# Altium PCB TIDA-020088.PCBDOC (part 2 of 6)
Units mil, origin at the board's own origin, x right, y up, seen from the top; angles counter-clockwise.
Board outline 7520.69 x 5119.11 mil, 6 copper layers (TOP, GND02, SIG03, SIG04, GND05, BOTTOM), stack 87.024 mil thick; 539 components, 269 nets, 1479 pads, 2085 vias.
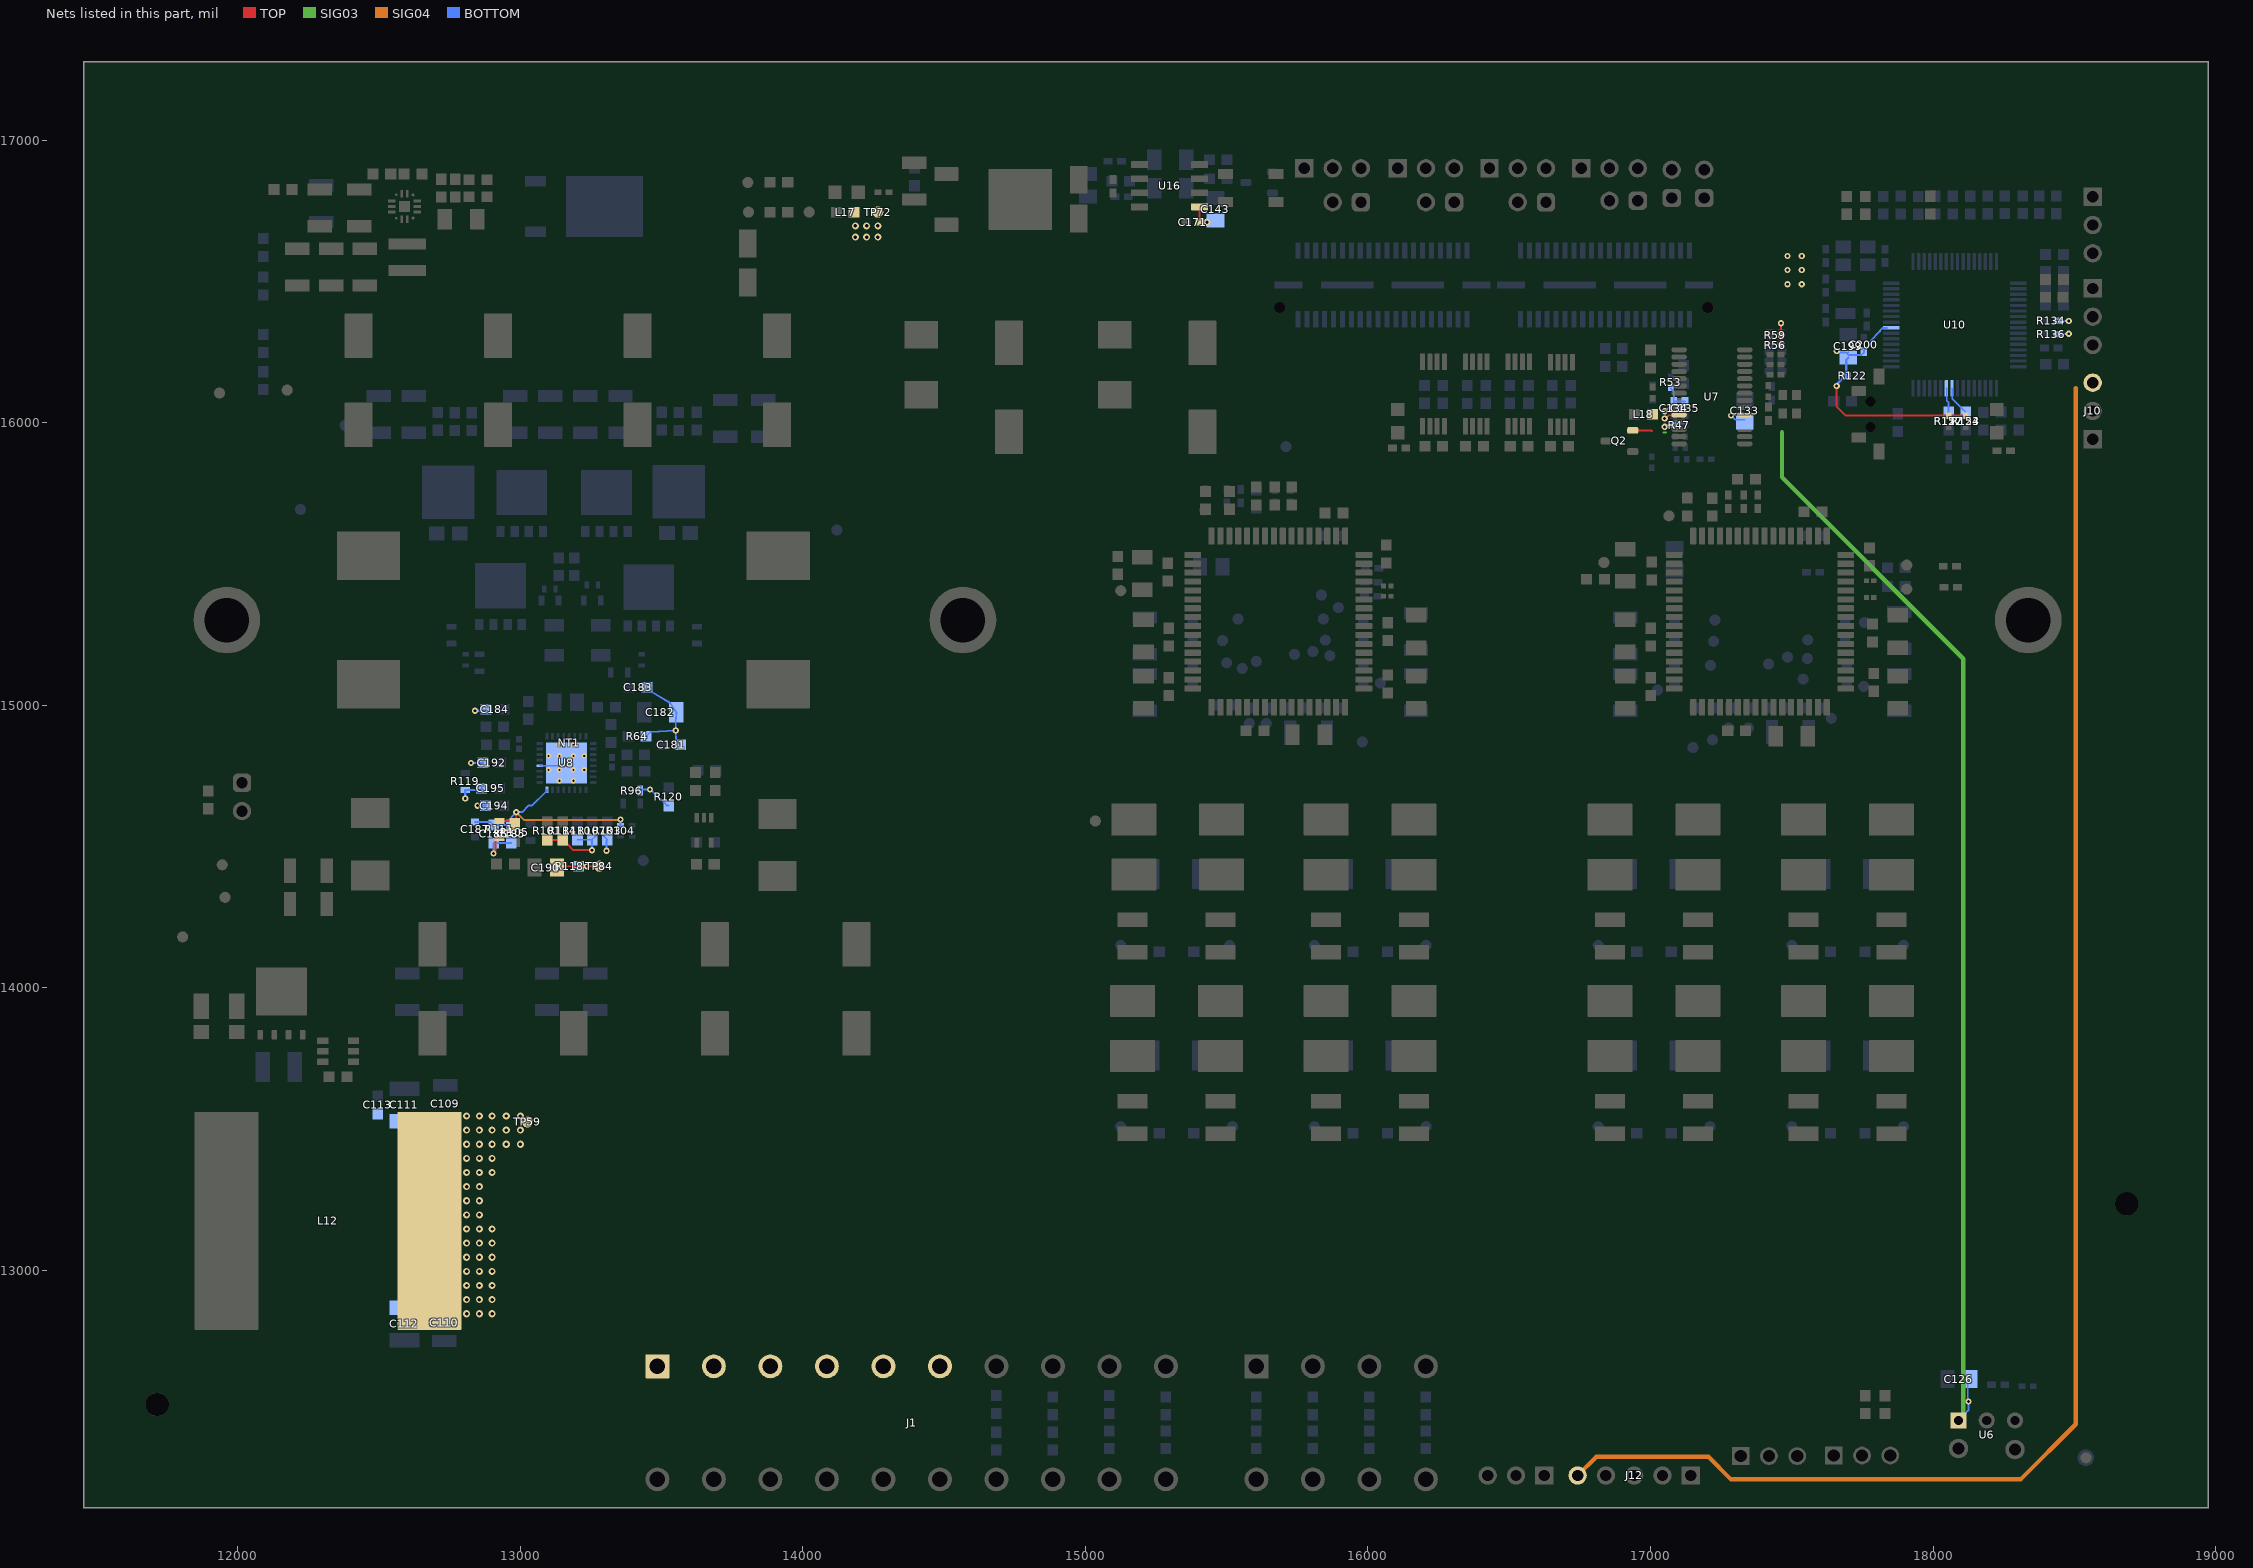
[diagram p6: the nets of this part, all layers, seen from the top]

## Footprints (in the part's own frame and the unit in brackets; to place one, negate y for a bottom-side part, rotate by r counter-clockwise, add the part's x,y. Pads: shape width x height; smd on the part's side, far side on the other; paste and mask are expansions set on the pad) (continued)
PM0064A-MFG [mm]
  rrect33% 1.5x0.3 smd paste+0 mask+0: 1(-5.7,3.75) 2(-5.7,3.25) 3(-5.7,2.75) 4(-5.7,2.25) 5(-5.7,1.75) 6(-5.7,1.25) 7(-5.7,0.75) 8(-5.7,0.25) 9(-5.7,-0.25) 10(-5.7,-0.75) 11(-5.7,-1.25) 12(-5.7,-1.75) 13(-5.7,-2.25) 14(-5.7,-2.75) 15(-5.7,-3.25) 16(-5.7,-3.75) 33(5.7,-3.75) 34(5.7,-3.25) 35(5.7,-2.75) 36(5.7,-2.25) 37(5.7,-1.75) 38(5.7,-1.25) 39(5.7,-0.75) 40(5.7,-0.25) 41(5.7,0.25) 42(5.7,0.75) 43(5.7,1.25) 44(5.7,1.75) 45(5.7,2.25) 46(5.7,2.75) 47(5.7,3.25) 48(5.7,3.75)
  rrect33% 0.3x1.5 smd paste+0 mask+0: 17(-3.75,-5.7) 18(-3.25,-5.7) 19(-2.75,-5.7) 20(-2.25,-5.7) 21(-1.75,-5.7) 22(-1.25,-5.7) 23(-0.75,-5.7) 24(-0.25,-5.7) 25(0.25,-5.7) 26(0.75,-5.7) 27(1.25,-5.7) 28(1.75,-5.7) 29(2.25,-5.7) 30(2.75,-5.7) 31(3.25,-5.7) 32(3.75,-5.7) 49(3.75,5.7) 50(3.25,5.7) 51(2.75,5.7) 52(2.25,5.7) 53(1.75,5.7) 54(1.25,5.7) 55(0.75,5.7) 56(0.25,5.7) 57(-0.25,5.7) 58(-0.75,5.7) 59(-1.25,5.7) 60(-1.75,5.7) 61(-2.25,5.7) 62(-2.75,5.7) 63(-3.25,5.7) 64(-3.75,5.7)
  silkscreen extent -7.13,-5.1 5.1,5.1, body extent -6,-6 6,6, height 1.6
PW0008A-MFG [mm]
  rrect22% 1.5x0.45 smd paste+0 mask+0: 1(-2.9,0.975) 2(-2.9,0.325) 3(-2.9,-0.325) 4(-2.9,-0.975) 5(2.9,-0.975) 6(2.9,-0.325) 7(2.9,0.325) 8(2.9,0.975)
  silkscreen extent -4.37,-1.55 1.77,1.55, body extent -3.75,-1.8 3.75,1.8, height 0.25
PW0028A_N [mm] "TSOP, 28-Leads, Body 9.7x4.4mm, Pitch 0.65mm, IPC Medium Density"
  oval 1.4x0.45 smd: 1(-2.95,4.225) 2(-2.95,3.575) 3(-2.95,2.925) 4(-2.95,2.275) 5(-2.95,1.625) 6(-2.95,0.975) 7(-2.95,0.325) 8(-2.95,-0.325) 9(-2.95,-0.975) 10(-2.95,-1.625) 11(-2.95,-2.275) 12(-2.95,-2.925) 13(-2.95,-3.575) 14(-2.95,-4.225) 15(2.95,-4.225) 16(2.95,-3.575) 17(2.95,-2.925) 18(2.95,-2.275) 19(2.95,-1.625) 20(2.95,-0.975) 21(2.95,-0.325) 22(2.95,0.325) 23(2.95,0.975) 24(2.95,1.625) 25(2.95,2.275) 26(2.95,2.925) 27(2.95,3.575) 28(2.95,4.225)
  silkscreen extent -3.5,-4.9 1.5,4.9, body extent -3.21,-4.85 3.21,4.85, height 1
RHB0032U-MFG [mm]
  rrect40% 0.6x0.25 smd paste+0 mask+0: 1(-2.4,1.75) 2(-2.4,1.25) 3(-2.4,0.75) 4(-2.4,0.25) 5(-2.4,-0.25) 6(-2.4,-0.75) 7(-2.4,-1.25) 8(-2.4,-1.75) 17(2.4,-1.75) 18(2.4,-1.25) 19(2.4,-0.75) 20(2.4,-0.25) 21(2.4,0.25) 22(2.4,0.75) 23(2.4,1.25) 24(2.4,1.75)
  rrect40% 0.25x0.6 smd paste+0 mask+0: 9(-1.75,-2.4) 10(-1.25,-2.4) 11(-0.75,-2.4) 12(-0.25,-2.4) 13(0.25,-2.4) 14(0.75,-2.4) 15(1.25,-2.4) 16(1.75,-2.4) 25(1.75,2.4) 26(1.25,2.4) 27(0.75,2.4) 28(0.25,2.4) 29(-0.25,2.4) 30(-0.75,2.4) 31(-1.25,2.4) 32(-1.75,2.4)
  rrect3% 3.7x3.7 smd paste-1000 mask+0: 33(0,0)
  silkscreen extent -3.37,-2.55 2.55,2.55, body extent -2.5,-2.5 2.5,2.5, height 1
RXB0014A-MFG [mm]
  round 0.225 smd paste+0 mask+0: 1(-0.75,1.05) 5(-0.75,-1.05)
  rrect40% 0.7x0.25 smd paste+0 mask+0: 2(-1.15,0.5) 3(-1.15,0) 4(-1.15,-0.5) 9(1.15,-0.5) 10(1.15,0) 11(1.15,0.5)
  rrect40% 0.25x0.7 smd paste+0 mask+0: 6(-0.25,-1.15) 7(0.25,-1.15) 13(0.25,1.15) 14(-0.25,1.15)
  round 0.27 smd paste+0 mask+0: 8(0.775,-1.05) 12(0.775,1.05)
  rrect10% 1x1 smd paste-1000 mask+0: 15(0,0)
  TOP region: -1.5,0.95 -1.5,1.1 -1.493,1.125 -1.475,1.143 -1.45,1.15 -1.45,1.15 -0.925,1.15 -0.906,1.154 -0.89,1.165 -0.879,1.181 -0.875,1.2 -0.875,1.2 -0.875,1.45 -0.868,1.475 -0.85,1.493 -0.825,1.5 -0.825,1.5 -0.675,1.5 -0.656,1.496 -0.64,1.485 -0.629,1.469 -0.625,1.45 -0.625,1.45 -0.625,0.95 -0.629,0.931 -0.64,0.915 -0.656,0.904 -0.675,0.9 -0.675,0.9 -1.45,0.9 -1.469,0.904 -1.485,0.915 -1.496,0.931 -1.5,0.95
  TOP region: 1.5,0.95 1.5,1.1 1.493,1.125 1.475,1.143 1.45,1.15 1.45,1.15 0.925,1.15 0.906,1.154 0.89,1.165 0.879,1.181 0.875,1.2 0.875,1.2 0.875,1.45 0.868,1.475 0.85,1.493 0.825,1.5 0.825,1.5 0.675,1.5 0.656,1.496 0.64,1.485 0.629,1.469 0.625,1.45 0.625,1.45 0.625,0.95 0.629,0.931 0.64,0.915 0.656,0.904 0.675,0.9 0.675,0.9 1.45,0.9 1.469,0.904 1.485,0.915 1.496,0.931 1.5,0.95
  TOP region: -1.5,-0.95 -1.5,-1.1 -1.493,-1.125 -1.475,-1.143 -1.45,-1.15 -1.45,-1.15 -0.925,-1.15 -0.906,-1.154 -0.89,-1.165 -0.879,-1.181 -0.875,-1.2 -0.875,-1.2 -0.875,-1.45 -0.868,-1.475 -0.85,-1.493 -0.825,-1.5 -0.825,-1.5 -0.675,-1.5 -0.656,-1.496 -0.64,-1.485 -0.629,-1.469 -0.625,-1.45 -0.625,-1.45 -0.625,-0.95 -0.629,-0.931 -0.64,-0.915 -0.656,-0.904 -0.675,-0.9 -0.675,-0.9 -1.45,-0.9 -1.469,-0.904 -1.485,-0.915 -1.496,-0.931 -1.5,-0.95
  TOP region: 1.5,-0.95 1.5,-1.1 1.493,-1.125 1.475,-1.143 1.45,-1.15 1.45,-1.15 0.925,-1.15 0.906,-1.154 0.89,-1.165 0.879,-1.181 0.875,-1.2 0.875,-1.2 0.875,-1.45 0.868,-1.475 0.85,-1.493 0.825,-1.5 0.825,-1.5 0.675,-1.5 0.656,-1.496 0.64,-1.485 0.629,-1.469 0.625,-1.45 0.625,-1.45 0.625,-0.95 0.629,-0.931 0.64,-0.915 0.656,-0.904 0.675,-0.9 0.675,-0.9 1.45,-0.9 1.469,-0.904 1.485,-0.915 1.496,-0.931 1.5,-0.95
  silkscreen extent -2.17,-1.68 1.58,1.68, body extent -1.6,-1.6 1.6,1.6, height 0.25
Samtec_HTSW-105-07-G-S [mm] "Samtec 100mil, 1x5, 230 mil above insulator"
  rrect6% 1.65x1.65 hole 1.016: 1(-5.08,0)
  round 1.65 hole 1.016: 2(-2.54,0) 3(0,0) 4(2.54,0) 5(5.08,0)
  silkscreen extent -7.11,-1.27 6.35,1.27, body extent -6.35,-1.27 6.35,1.27, height 8.38
SO-8FL [mm] "ON SEMICONDUCTOR, DFN5 5x6, 1.27P, CASE 488AA"
  rect 1x0.75 smd: 1(-2.795,1.905) 2(-2.795,0.635) 3(-2.795,-0.635) 4(-2.795,-1.905)
  rect 4.055x4.56 smd: 5(0.698,0)
  TOP region: 2.65,-2.279 2.65,-1.529 3.2,-1.529 3.2,-2.279
  TOP region: 2.655,1.531 2.655,2.281 3.2,2.281 3.2,1.531
  TOP region: -0.905,-2.775 -0.905,2.775 0,2.775 0,-2.775
  silkscreen extent -3.1,-2.6 3.1,2.9, body extent -3.17,-2.67 3.17,2.67, height 1.11
SOD-123HE [mm] "SMD, 2-Leads, Body 2.8x1.8mm"
  rect 2.3x1.4 smd: 1(-0.9,0)
  rect 1.25x1.4 smd: 2(1.425,0)
  silkscreen extent -2.7,-1.1 2,1.1, body extent -1.5,-0.97 1.5,0.97, height 1
SOT-23 [mm] "SOT23, 3-Leads, Body 2.9x1.3mm, Pitch 0.95mm, Lead Span 2.5mm, IPC Medium Density"
  rrect50% 1x0.6 smd: 1(-1.2,0.95) 2(-1.2,-0.95) 3(1.2,0)
  silkscreen extent -1.63,-1.5 0.7,1.5, body extent -1.16,-1.45 1.21,1.45, height 1
SRP2313AA [mm] "Shielded, metal alloy powder core"
  rrect2% 5.75x19.6 smd: 1(-9.125,0) 2(9.125,0)
  body extent -11.75,-11 11.75,11, height 12.61
SW_1188E [mm] "SMD, 4-Leads, Body 7.8x3.5mm"
  rrect10% 1x1.45 smd: 1(-1.1,3.375) 2(-1.1,-3.375)
  rrect11% 1.3x0.9 smd: 3(0.7,2.1) 4(0.7,-2.1)
  round 0 hole 0.9 unplated: ""(-0.35,1.15) ""(-0.35,-1.15)
  silkscreen extent -1.97,-2.28 0.95,2.28, body extent -2.55,-3.9 1.05,3.9, height 3.5
TI_Stacked_Overlay_Small [mil]
  silkscreen extent -418,-98 418,98
TO-277A [mm] "Vishay"
  rect 1.4x1.27 smd: 1(-1.04,1.83) 2(1.04,1.83)
  rect 4.72x4.8 smd: 3(0,-1.883)
  silkscreen extent -2.7,1.45 -2.4,1.75, body extent -2.35,-4.2 2.4,2.45, height 1.2
TP_SM_1MM [mm] "1mm Test Point, SMT"
  round 1 smd paste-0.5: 1(0,0)
TSW-102-07-G-S [mm] "Samtec 100mil, 1x2, 230 mil above insulator"
  rrect50% 1.65x1.65 hole 1.016: 1(-1.27,0)
  round 1.65 hole 1.016: 2(1.27,0)
  body extent -2.54,-1.27 2.54,1.27, height 8.38
ULRB22512_085 [mm] "SMD, 4-Leads, Body 6.35x3.18mm"
  rect 2.7x3.45 smd: 1(-2.8,0) 2(2.8,0)
  silkscreen extent -1,-1.72 1,1.72, body extent -3.3,-1.72 3.3,1.72, height 0.85
WEEE_Minimum [mil] "WEEElie bin"
  silkscreen extent -95,-172 99,104
Wurth_61300311021 [mm] "Header, 2.54 mm, 3x1, R/A, TH"
  rect 1.6x1.6 hole 1.1: 1(-2.54,0)
  round 1.6 hole 1.1: 2(0,0) 3(2.54,0)
  silkscreen extent -4.25,-4.04 3.81,-1.5, body extent -3.81,-10.04 3.81,0.32, height 2.55
XTAL_ABM10 [mm] "ABRACON"
  rect 0.8x0.9 smd: 1(-0.625,0.825) 2(-0.625,-0.825) 3(0.625,-0.825) 4(0.625,0.825)
  silkscreen extent -1.28,-0.13 1.05,1.52, body extent -1.05,-1.3 1.05,1.3, height 0.7

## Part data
C1 C4 C5 C9 C12 C53 C56 C57 C61 C64 C208 C210 C212 C214: library part CMP-0007139-3, "CAP, CERM, 1 uF, 25 V, +/- 10%, X7R, AEC-Q200 Grade 1, 0603", Cap_Case=0603, Manufacturer=MuRata, Supplier Part Number 1=490-10673-1-ND, TempCo=X7R, Tolerance_%=10%, Value1=Unknown, Value2=25V, ValueDisplayed=1uF
C2 C6 C10 C13 C15 C17 C54 C58 C62 C65 C67 C69 C122 C182: library part CMP-0750040-1, "CAP, CERM, 1 µF, 100 V,+/- 10%, X7R, AEC-Q200 Grade 1, 1206", Cap_Case=1206, Manufacturer=MuRata, TempCo=X7R, Tolerance_%=10%, Value2=100V, ValueDisplayed=1µF
C3 C7 C11 C14 C16 C18 C55 C59 C63 C66 C68 C70 C193 C203: library part CMP-0064935-2, "CAP, CERM, 0.1 uF, 100 V,+/- 10%, X7R, AEC-Q200 Grade 1, 0603", Cap_Case=0603, Manufacturer=MuRata, Supplier Part Number 1=490-13420-1-ND, TempCo=X7R, Tolerance_%=10%, Value1=Unknown, Value2=100V, ValueDisplayed=0.1uF
C8 C60: library part CMP-0083622-1, "CAP, CERM, 2.2 µF, 25 V,+/- 10%, X7R, AEC-Q200 Grade 1, 0805", Cap_Case=0805, Manufacturer=MuRata, Supplier Part Number 1=490-4787-1-ND, TempCo=X7R, Tolerance_%=10%, Value2=25V, ValueDisplayed=2.2µF
C19 C22 C29 C30 C37 C38 C45 C46 C71 C74 C81 C82 C89 C90 C97 C98: library part CMP-0007145-4, "CAP, CERM, 0.22 uF, 50 V, +/- 10%, X7R, AEC-Q200 Grade 1, 0603", Cap_Case=0603, Manufacturer=MuRata, Supplier Part Number 1=490-5402-1-ND, TempCo=X7R, Tolerance_%=10%, Value1=Unknown, Value2=50V, ValueDisplayed=0.22uF
C20 C21 C72 C73: library part CMP-0009660-3, "CAP, CERM, 100 pF, 25 V, +/- 10%, X7R, AEC-Q200 Grade 1, 0201", Cap_Case=0201, Manufacturer=MuRata, Supplier Part Number 1=GCM033R71E101KA03D-ND, TempCo=X7R, Tolerance_%=10%, Value1=Unknown, Value2=25V, ValueDisplayed=100pF
C23 C24 C31 C32 C39 C40 C47 C48 C75 C76 C83 C84 C91 C92 C99 C100: library part CMP-0007145-4, "CAP, CERM, 0.22 uF, 50 V, +/- 10%, X7R, AEC-Q200 Grade 1, 0603", Cap_Case=0603, Manufacturer=MuRata, PartNumber=GCM188R71H224KA64D, Supplier Part Number 1=490-5402-1-ND, TempCo=X7R, Tolerance_%=10%, Value1=Unknown, Value2=50V, ValueDisplayed=0.22uF
C25 C26 C33 C34 C41 C42 C49 C50 C77 C78 C85 C86 C93 C94 C101 C102: library part CMP-0009152-2, "CAP, CERM, 2.2 uF, 100 V, +/- 10%, X7R, AEC-Q200 Grade 1,", Cap_Case=1210_250, Manufacturer=TDK, Supplier Part Number 1=445-5866-1-ND, TempCo=X7R, Tolerance_%=10%, Value1="0.00173 ohm", Value2=100V, ValueDisplayed=2.2uF
C27 C28 C35 C36 C43 C44 C51 C52 C79 C80 C87 C88 C95 C96 C103 C104 C185 C186: library part CMP-0007082-4, "CAP, CERM, 0.01 uF, 100 V, +/- 10%, X7R, AEC-Q200 Grade 1, 0603", Cap_Case=0603, Manufacturer=TDK, Supplier Part Number 1=445-5812-1-ND, TempCo=X7R, Tolerance_%=10%, Value1="0.235428 ohm", Value2=100V, ValueDisplayed=0.01uF
C105 C138 C140: library part CMP-0007139-4, "CAP, CERM, 1 uF, 25 V, +/- 10%, X7R, AEC-Q200 Grade 1, 0603", Cap_Case=0603, Manufacturer=MuRata, Supplier Part Number 1=490-10673-1-ND, TempCo=X7R, Tolerance_%=10%, Value1=Unknown, Value2=25V, ValueDisplayed=1uF
C106 C114: library part CMP-0860542-1, "CAP, AL, 47 µF, 16 V, +/- 20%, 0.85 ohm, AEC-Q200 Grade 2, SMD", Cap_Case=B, Manufacturer=Panasonic, Tolerance_%=20%, Value1="0.85 ohm", Value2=16V, ValueDisplayed=47µF
C107 C111 C112: library part CMP-0750153-1, "CAP, CERM, 4.7 µF, 50 V,+/- 10%, X7R, AEC-Q200 Grade 1, 1210", Cap_Case=1210, Manufacturer=MuRata, TempCo=X7R, Tolerance_%=10%, Value2=50V, ValueDisplayed=4.7µF
C108 C109 C110 C117 C118 C120 C121 C139 C144 C145 C146 C147 C150 C151 C152 C153 C155 C156 C157 C158 C216 C217 C218 C219 C220 C221 C222 C223 C224 C225: library part CMP-0009258-2, "CAP, CERM, 10 uF, 50 V, +/- 10%, X7R, AEC-Q200 Grade 1, 1210", Cap_Case=1210, Manufacturer="Taiyo Yuden", Supplier Part Number 1=587-4326-1-ND, TempCo=X7R, Tolerance_%=10%, Value1=Unknown, Value2=50V, ValueDisplayed=10uF
C113 C141 C142 C148 C149 C167 C168 C169 C170 C179 C180 C181 C183 C184 C209 C211 C213 C215: library part CMP-0064935-4, "CAP, CERM, 0.1 uF, 100 V,+/- 10%, X7R, AEC-Q200 Grade 1, 0603", Cap_Case=0603, Manufacturer=MuRata, Supplier Part Number 1=490-13420-1-ND, TempCo=X7R, Tolerance_%=10%, Value1=Unknown, Value2=100V, ValueDisplayed=0.1uF
C115 C116 C159 C160 C161 C162 C163 C164 C165 C166: library part CMP-0064900-1, "CAP, AL, 330 uF, 50 V, +/- 20%, SMD", Cap_Case=10x10mm, Manufacturer=Nichicon, Supplier Part Number 1=493-14535-1-ND, Tolerance_%=20%, Value1=Unknown, Value2=50V, ValueDisplayed=330uF
C119 C194: library part CMP-0084283-1, "CAP, CERM, 10 pF, 100 V,+/- 5%, C0G/NP0, AEC-Q200 Grade 1, 0603", Cap_Case=0603, Manufacturer=MuRata, TempCo=C0G/NP0, Tolerance_%=5%, Value2=100V, ValueDisplayed=10pF
C123 C124 C125: library part CMP-0009154-2, "CAP, CERM, 22 uF, 16 V, +/- 20%, X7R, AEC-Q200 Grade 1, 1210", Cap_Case=1210_280, Manufacturer=TDK, Supplier Part Number 1=445-5723-1-ND, TempCo=X7R, Tolerance_%=20%, Value1="0.002582 ohm", Value2=16V, ValueDisplayed=22uF
C126 C133 C143 C154 C189 C199: library part CMP-0081061-1, "CAP, CERM, 10 µF, 10 V,+/- 5%, X7R, AEC-Q200 Grade 1, 0805", Cap_Case=0805, Manufacturer=Kemet, Supplier Part Number 1=399-15693-1-ND, TempCo=X7R, Tolerance_%=5%, Value2=10V, ValueDisplayed=10µF
C127 C130 C131 C132: library part CMP-0860290-1, "CAP, CERM, 10 pF, 50 V,+/- 5%, C0G/NP0, AEC-Q200 Grade 1, 0402", Cap_Case=0402, Manufacturer=MuRata, TempCo=C0G/NP0, Tolerance_%=5%, Value2=50V, ValueDisplayed=10pF
C128 C129 C173 C204: library part CMP-0085255-1, "CAP, CERM, 20 pF, 50 V,+/- 5%, C0G/NP0, AEC-Q200 Grade 1, 0402", Cap_Case=0402, Manufacturer=MuRata, TempCo=C0G/NP0, Tolerance_%=5%, Value2=50V, ValueDisplayed=20pF
C134 C135 C206 C207: library part CMP-0080702-1, "CAP, CERM, 0.1 µF, 16 V,+/- 5%, X7R, AEC-Q200 Grade 1, 0402", Cap_Case=0402, Manufacturer=MuRata, Supplier Part Number 1=490-16433-1-ND, TempCo=X7R, Tolerance_%=5%, Value2=16V, ValueDisplayed=0.1µF
C136: library part CMP-0006361-2, "CAP, CERM, 4700 pF, 50 V, +/- 10%, X7R, AEC-Q200 Grade 1, 0402", Cap_Case=0402, Manufacturer=MuRata, Supplier Part Number 1=490-4915-1-ND, TempCo=X7R, Tolerance_%=10%, Value1=Unknown, Value2=50V, ValueDisplayed=4700pF
C137: library part CMP-0007080-5, "CAP, CERM, 0.068 uF, 50 V, +/- 10%, X7R, AEC-Q200 Grade 1, 0603", Cap_Case=0603, Manufacturer=TDK, Supplier Part Number 1=445-5665-1-ND, TempCo=X7R, Tolerance_%=10%, Value1="0.035979 ohm", Value2=50V, ValueDisplayed=0.068uF
C171 C172 C200: library part CMP-0006356-2, "CAP, CERM, 0.1 uF, 50 V, +/- 10%, X7R, AEC-Q200 Grade 1, 0402", Cap_Case=0402, Manufacturer=MuRata, Supplier Part Number 1=490-10672-1-ND, TempCo=X7R, Tolerance_%=10%, Value1=Unknown, Value2=50V, ValueDisplayed=0.1uF
C174: library part CMP-0007146-4, "CAP, CERM, 4700 pF, 50 V, +/- 10%, X7R, AEC-Q200 Grade 1, 0603", Cap_Case=0603, Manufacturer=MuRata, Supplier Part Number 1=490-4932-1-ND, TempCo=X7R, Tolerance_%=10%, Value1=Unknown, Value2=50V, ValueDisplayed=4700pF
C175 C176: library part CMP-0006960-4, "CAP, CERM, 680 pF, 50 V, +/- 10%, X7R, 0603", Cap_Case=0603, Manufacturer=Kemet, PartNumber=C0603C681K5RACTU, Supplier Part Number 1=399-1077-1-ND, TempCo=X7R, Tolerance_%=10%, Value1=Unknown, Value2=50V, ValueDisplayed=680pF
C177 C178: library part CMP-06035-033140-1, "Ceramic Capacitor for Automotive 68pF ±1% 50VDC C0G 0402 Paper T/R", Capacitance=68pF, Case Code (Imperial)=0402, Case Code (Metric)=1005, Max Operating Temperature=125°C, Min Operating Temperature=-55°C, Ratings=AEC-Q200, Tolerance=1%, Voltage Rating=50V
C187 C188: library part CMP-0084117-1, "0.047µF ±10% 50V Ceramic Capacitor X7R 0603 (1608 Metric)", Digikey Part Number=490-5854-1-ND, Manufacturer="Murata Electronics North America", Mouser Part Number=81-GCJ188R71H473KA2D, Operating Temperature Range="-55°C to +125°C", TempCo=15%, Temperature Characteristic=X7R, Tolerance_%=10%, ValueDisplayed=47nF
C190: library part CMP-0007963-2, "CAP, CERM, 3.3 uF, 35 V, +/- 10%, X7R, AEC-Q200 Grade 1, 0805", Cap_Case=0805, Manufacturer=TDK, Supplier Part Number 1=810-CGA4J1X7R1V335K125AC, TempCo=X7R, Tolerance_%=10%, Value1="0.002798 ohm", Value2=35V, ValueDisplayed=3.3uF
C191: library part CMP-0080737-1, "CAP, CERM, 0.015 µF, 16 V,+/- 2%, C0G/NP0, AEC-Q200 Grade 1, 0603", Cap_Case=0603, Manufacturer=Kemet, Supplier Part Number 1=399-9963-1-ND, TempCo=C0G/NP0, Tolerance_%=2%, Value2=16V, ValueDisplayed=0.015µF
C192: library part CMP-0007127-4, "CAP, CERM, 470 pF, 50 V, +/- 5%, C0G/NP0, AEC-Q200 Grade 1, 0603", Cap_Case=0603, Manufacturer=MuRata, Supplier Part Number 1=490-4965-1-ND, TempCo=C0G/NP0, Tolerance_%=5%, Value1=Unknown, Value2=50V, ValueDisplayed=470pF
C195: library part CMP-0007095-4, "CAP, CERM, 0.33 uF, 50 V, +/- 10%, X7R, AEC-Q200 Grade 1, 0603", Cap_Case=0603, Manufacturer=TDK, Supplier Part Number 1=445-174426-1-ND, TempCo=X7R, Tolerance_%=10%, Value1="0.01584 ohm", Value2=50V, ValueDisplayed=0.33uF
C196 C197 C198 C202: library part CMP-0006348-2, "CAP, CERM, 22 pF, 50 V, +/- 5%, C0G/NP0, AEC-Q200 Grade 1, 0402", Cap_Case=0402, Manufacturer=MuRata, Supplier Part Number 1=490-9648-1-ND, TempCo=C0G/NP0, Tolerance_%=5%, Value1=Unknown, Value2=50V, ValueDisplayed=22pF
C201: library part CMP-0007142-4, "CAP, CERM, 0.47 uF, 25 V, +/- 10%, X7R, AEC-Q200 Grade 1, 0603", Cap_Case=0603, Manufacturer=MuRata, Supplier Part Number 1=490-4776-1-ND, TempCo=X7R, Tolerance_%=10%, Value1=Unknown, Value2=25V, ValueDisplayed=0.47uF
D1 D2: library part CMP-0028825-2, "Diode, Schottky, 60 V, 3 A, AEC-Q101, SOD-123HE", Manufacturer="Fairchild Semiconductor", Value1=3A, Value2=0.65V
D3: "LED, Green, SMD", Color=Green, Manufacturer=Lite-On, PartNumber=LTST-C170KGKT, Supplier Part Number 1=160-1414-1-ND, Value1=W, Value2=2V
D4: "LED, Blue, SMD", Color=blue, Manufacturer=Rohm, PartNumber=SMLP12BC7TT86, Supplier Part Number 1=511-1615-1-ND, Value1=W, Value2=2.9V
D5 D6: library part CMP-0028832-2, "Diode, Schottky, 100 V, 12 A, AEC-Q101, TO-277A", Manufacturer=Vishay-Semiconductor, Value1=12A, Value2=0.7V
D7 D8: library part CMP-0002829-3, "LED, Red, SMD", Color=red, Manufacturer=Lite-On, Value1=W, Value2=2V
D9: library part CMP-0005920-3, "Diode, TVS, Bi, 24 V, 70 Vc, AEC-Q101, SOT-23", Manufacturer="NXP Semiconductor", Value1=200W
J1: library part CMP-0087217-1, "TERM BLOCK HDR 20POS 5.08MM", Current_A=10A, Manufacturer="Phoenix Contact", Voltage_V=320V
J2 J4 J6 J10 J13 J14 J16 J21: library part CMP-0002334-1, "Header, 100mil, 3x1, Gold, TH", Manufacturer="Sullins Connector Solutions", Supplier Part Number 1=S1011E-03-ND
J3 J17 J18 J19 J20 J22: library part CMP-0075405-2, "Header, 100mil, 2x1, Gold, TH", Color=Black, Current_A=6.3A, Manufacturer=Samtec, Supplier Part Number 1=SAM1029-02-ND, Voltage_V=550V
J5: library part CMP-0093062-1, Current_A=10A, Digikey Part Number=277-1401-ND, Manufacturer="Phoenix Contact", Mouser Part Number=651-1736713, Operating Temperature Range="-40°C to +100°C", Voltage_V=320V
J7 J8: library part CMP-0075020-1, "JUMPER TIN SMD", Manufacturer=Harwin, PartNumber=S1911-46R, Supplier Part Number 1=952-1740-1-ND
J9: library part CMP-0075405-3, "Header, 100mil, 2x1, Gold, TH", Color=Black, Current_A=6.3A, Manufacturer=Samtec, Supplier Part Number 1=SAM1029-02-ND, Voltage_V=550V
J11 J23: library part CMP-0054795-1, "Header, 2.54 mm, 3x1, Gold, R/A, TH", Color=Black, Manufacturer="Wurth Elektronik", Supplier Part Number 1=732-5336-ND
J12: library part CMP-0075485-1, "Header, 100mil, 5x1, Gold, TH", Manufacturer=Samtec, Supplier Part Number 1=SAM8737-ND
J15: library part CMP-0091968-1, "80 Position Connector Header, Outer Shroud Contacts Surface Mount Gold", Digikey Part Number=SAM8132-ND, Manufacturer=Samtec, Mouser Part Number=200-QTE04001LDA, Operating Temperature Range="-55°C to +125°C", Voltage_V=225V
L1 L6 L13 L16 L17 L18 L21: library part CMP-0084877-1, "Inductor, Ferrite Bead, Ferrite, 3 A, 120 ohm, AEC-Q200 Grade 1, SMD", Manufacturer=MuRata, Value1="120 ohm", Value2=3A
L2 L3 L4 L5 L7 L8 L9 L10: library part CMP-0093075-1, "Power Choke Coil, 10uH 20% 100kHz, 22mΩ DCR max, Idc 5.8A, Isat 10A", Manufacturer=Cyntec, Operating Temperature Range="-55°C to +125°C", Test Frequency=100kHz, Tolerance_%=20%
L11 L14: library part CMP-0084877-1, "Inductor, Ferrite Bead, Ferrite, 3 A, 120 ohm, AEC-Q200 Grade 1, SMD", Manufacturer=MuRata, PartNumber=BLM18SG121TZ1D, Value1="120 ohm", Value2=3A
L12: library part CMP-0081035-1, "Inductor, Shielded, Metal Composite, 1 µH, 60 A, 0.00095 ohm, AEC-Q200 Grade 0, SMD", Manufacturer=Bourns, Supplier Part Number 1=652-SRP2313AA-1R0M, Value1="0.00095 ohm", Value2=60A, ValueDisplayed=1µH
L15: library part CMP-0120010-1, "Ultra-Low Loss Shielded Power Inductors 2.2µH ±20% 7.8A 22.1mOhms", Manufacturer=Coilcraft, Mouser Part Number=994-XEL4030-222MEC, Operating Temperature Range=to, Self Resonant Frequency=40MHz, Test Frequency=1MHz, Tolerance_%=20%
L19 L20: library part CMP-0122777-1, "Power Choke Coil 3.3uH 20% 100kHz 22.9A 6.6mOhm, 13.45x12.6x6.3mm SMT AECQ200", Manufacturer=Cyntec, Operating Temperature Range="-55°C to +125°C", Test Frequency=100kHz, Tolerance_%=20%
L22: library part CMP-0062430-2, "Inductor, Ferrite, 100 uH, 0.15 A, 2 ohm, SMD", Manufacturer=TDK, Supplier Part Number 1=445-3959-1-ND, Value1="2 ohm", Value2=0.15A, ValueDisplayed=100uH
Logo2: library part CMP-0074838-1, "Texas Instrument Corporate Signature"
Logo6: library part CMP-0074844-1
Logo7: library part CMP-0074847-1, "FCC_disclaimer"
Logo8: library part CMP-0074769-1
NT1: library part CMP-0078142-6, "Single point connection between nets.", Manufacturer=N/A
Q1: library part CMP-0000274-1, "MOSFET, N-CH, 25 V, 100 A, DNK0008A (VSON-CLIP-8)", Alternate Manufacturer=None, Manufacturer="Texas Instruments", Supplier Part Number 1=CSD16570Q5B-ND, Value1=0, Value2="192 nC"
Q2: library part CMP-0000325-2, "Transistor, PNP, 40 V, 0.2 A, SOT-23", Manufacturer="Fairchild Semiconductor", Supplier Part Number 1=MMBT3906FSCT-ND, Value1="0.2 A", Value2=300
Q3 Q4 Q5 Q6: library part CMP-0000853-1, "MOSFET, N-CH, 60 V, 71 A, SO-8FL", Alternate Manufacturer=None, Manufacturer="ON Semiconductor", PartNumber=NTMFS5C670NLT1G, Supplier Part Number 1=NTMFS5C670NLT1GOSCT-ND, Value1=0.008, Value2="20 nC"
R1 R3 R6 R20 R22 R25: library part CMP-0025958-3, "RES, 10.0 k, 1%, 0.063 W, AEC-Q200 Grade 0, 0402", Manufacturer=Vishay-Dale, Power_W=63mW, Supplier Part Number 1=541-10.0KLCT-ND, TempCo="100 ppm/C", Tolerance_%=1%, Value2=0.063W, Value_Code=10k0, ValueDisplayed=10.0k
R2 R4 R8 R10 R12 R13 R14 R17 R21 R23 R27 R28 R30 R31 R32 R33: library part CMP-0015017-3, "RES, 0, 1%, 0.75 W, AEC-Q200 Grade 0, 1210", Manufacturer=Vishay-Dale, Power_W=750mW, Supplier Part Number 1=541-0.0NCT-ND, TempCo=ppm/C, Tolerance_%=1%, Value2=0.75W, Value_Code=0
R5 R15 R16 R24 R134 R136: library part CMP-0026231-2, "RES, 2.20 k, 1%, 0.063 W, AEC-Q200 Grade 0, 0402", Manufacturer=Vishay-Dale, Power_W=63mW, Supplier Part Number 1=541-2.20KLCT-ND, TempCo="100 ppm/C", Tolerance_%=1%, Value2=0.063W, Value_Code=2k20, ValueDisplayed=2.20k
R7 R26: library part CMP-0025958-3, "RES, 10.0 k, 1%, 0.063 W, AEC-Q200 Grade 0, 0402", Manufacturer=Vishay-Dale, PartNumber=CRCW040210K0FKED, Power_W=63mW, Supplier Part Number 1=541-10.0KLCT-ND, TempCo="100 ppm/C", Tolerance_%=1%, Value2=0.063W, Value_Code=10k0, ValueDisplayed=10.0k
R9 R18 R35 R36 R40 R68 R80 R101 R113 R115 R125 R130 R132 R133 R144 R145 R146 R172: library part CMP-0025697-4, "RES, 0, 5%, 0.1 W, AEC-Q200 Grade 0, 0603", Manufacturer=Vishay-Dale, PartNumber=CRCW06030000Z0EA, Power_W=100mW, Supplier Part Number 1=541-0.0GCT-ND, TempCo="200 ppm/C", Tolerance_%=5%, Value2=0.1W, Value_Code=0000, ValueDisplayed=0
R11 R19 R29 R37 R38 R41 R60 R61 R66 R67 R70 R71 R79 R83 R87 R88 R89 R90 R97 R102 R103 R109 R114 R123 R124 R127 R128 R137 R138 R140 R141 R142 R143 R147 R150 R151 R157 R158 R166 R167: library part CMP-0025697-4, "RES, 0, 5%, 0.1 W, AEC-Q200 Grade 0, 0603", Manufacturer=Vishay-Dale, Power_W=100mW, Supplier Part Number 1=541-0.0GCT-ND, TempCo="200 ppm/C", Tolerance_%=5%, Value2=0.1W, Value_Code=0000, ValueDisplayed=0
R34 R39 R54: library part CMP-0026852-3, "RES, 1.0 k, 5%, 0.063 W, AEC-Q200 Grade 0, 0402", Manufacturer=Vishay-Dale, Power_W=63mW, Supplier Part Number 1=541-1.0KJCT-ND, TempCo="200 ppm/C", Tolerance_%=5%, Value2=0.063W, Value_Code=1k00, ValueDisplayed=1.0k
R42 R43 R44 R46 R48: "RES, 49.9, 1%, 0.063 W, AEC-Q200 Grade 0, 0402", Manufacturer=Vishay-Dale, PartNumber=CRCW040249R9FKED, Power_W=63mW, Supplier Part Number 1=541-49.9LCT-ND, TempCo="100 ppm/C", Tolerance_%=1%, Value2=0.063W, Value_Code=49R9, ValueDisplayed=49.9
R45: library part CMP-0026934-3, "RES, 470, 5%, 0.063 W, AEC-Q200 Grade 0, 0402", Manufacturer=Vishay-Dale, Power_W=63mW, Supplier Part Number 1=541-470JCT-ND, TempCo="200 ppm/C", Tolerance_%=5%, Value2=0.063W, Value_Code=470R, ValueDisplayed=470
R47 R50 R56 R58: "RES, 4.99 k, 1%, 0.063 W, AEC-Q200 Grade 0, 0402", Manufacturer=Vishay-Dale, PartNumber=CRCW04024K99FKED, Power_W=63mW, Supplier Part Number 1=541-4.99KLCT-ND, TempCo="100 ppm/C", Tolerance_%=1%, Value2=0.063W, Value_Code=4k99, ValueDisplayed=4.99k
R49: library part CMP-0022496-4, "RES, 560 k, 1%, 0.1 W, AEC-Q200 Grade 0, 0603", Manufacturer=Vishay-Dale, Power_W=100mW, Supplier Part Number 1=541-560KHCT-ND, TempCo="100 ppm/C", Tolerance_%=1%, Value2=0.1W, Value_Code=560k
R51 R63 R64: library part CMP-0022324-4, "RES, 30.1 k, 1%, 0.1 W, AEC-Q200 Grade 0, 0603", Manufacturer=Vishay-Dale, Power_W=100mW, Supplier Part Number 1=541-30.1KHCT-ND, TempCo="100 ppm/C", Tolerance_%=1%, Value2=0.1W, Value_Code=30k1, ValueDisplayed=30.1k
R52: "RES, 681, 1%, 0.063 W, AEC-Q200 Grade 0, 0402", Manufacturer=Vishay-Dale, PartNumber=CRCW0402681RFKED, Power_W=63mW, Supplier Part Number 1=541-681LCT-ND, TempCo="100 ppm/C", Tolerance_%=1%, Value2=0.063W, Value_Code=681R, ValueDisplayed=681
R53: "RES, 100 k, 1%, 0.063 W, AEC-Q200 Grade 0, 0402", Manufacturer=Vishay-Dale, PartNumber=CRCW0402100KFKED, Power_W=63mW, Supplier Part Number 1=541-100KLCT-ND, TempCo="100 ppm/C", Tolerance_%=1%, Value2=0.063W, Value_Code=100k
R55 R59: library part CMP-0026414-2, "RES, 4.99 k, 1%, 0.063 W, AEC-Q200 Grade 0, 0402", Manufacturer=Vishay-Dale, PartNumber=CRCW04024K99FKED, Power_W=63mW, Supplier Part Number 1=541-4.99KLCT-ND, TempCo="100 ppm/C", Tolerance_%=1%, Value2=0.063W, Value_Code=4k99, ValueDisplayed=4.99k
R57 R152 R153: "RES, 10.0 k, 1%, 0.063 W, AEC-Q200 Grade 0, 0402", Manufacturer=Vishay-Dale, PartNumber=CRCW040210K0FKED, Power_W=63mW, Supplier Part Number 1=541-10.0KLCT-ND, TempCo="100 ppm/C", Tolerance_%=1%, Value2=0.063W, Value_Code=10k0, ValueDisplayed=10.0k
R62 R94: library part CMP-0025725-4, "RES, 180 k, 5%, 0.1 W, AEC-Q200 Grade 0, 0603", Manufacturer=Vishay-Dale, Power_W=100mW, Supplier Part Number 1=541-180KGCT-ND, TempCo="200 ppm/C", Tolerance_%=5%, Value2=0.1W, Value_Code=180k
R69 R72: library part CMP-0017672-3, "RES, 60.4, 1%, 0.25 W, AEC-Q200 Grade 0, 1206", Manufacturer=Panasonic, Power_W=250mW, Supplier Part Number 1=P60.4FCT-ND, TempCo="100 ppm/C", Tolerance_%=1%, Value2=0.25W, Value_Code=60R4, ValueDisplayed=60.4
R73 R74: library part CMP-0022306-4, "RES, 2.21, 1%, 0.1 W, AEC-Q200 Grade 0, 0603", Manufacturer=Vishay-Dale, Power_W=100mW, Supplier Part Number 1=541-2.21HHCT-ND, TempCo="100 ppm/C", Tolerance_%=1%, Value2=0.1W, Value_Code=2R21, ValueDisplayed=2.21
R75 R76 R92 R93 R99: library part CMP-0025950-3, "RES, 100 k, 1%, 0.063 W, AEC-Q200 Grade 0, 0402", Manufacturer=Vishay-Dale, Power_W=63mW, Supplier Part Number 1=541-100KLCT-ND, TempCo="100 ppm/C", Tolerance_%=1%, Value2=0.063W, Value_Code=100k
R77 R78: library part CMP-0015847-2, "RES, 0.0015, 1%, 2 W, AEC-Q200 Grade 0, 2512", Manufacturer="TT Electronics/IRC", Power_W=2W, Supplier Part Number 1=66-ULRB2R0015FLFSLT, TempCo="50 ppm/C", Tolerance_%=1%, Value_Code=1L500, ValueDisplayed=0.0015
R84 R85: library part CMP-0022003-4, "RES, 10.0, 1%, 0.1 W, AEC-Q200 Grade 0, 0603", Manufacturer=Vishay-Dale, Power_W=100mW, Supplier Part Number 1=541-10.0HCT-ND, TempCo="100 ppm/C", Tolerance_%=1%, Value2=0.1W, Value_Code=10R0, ValueDisplayed=10.0
R86 R91: library part CMP-0016971-3, "RES, 3.24, 1%, 0.25 W, AEC-Q200 Grade 0, 1206", Manufacturer=Vishay-Dale, PartNumber=CRCW12063R24FKEA, Power_W=250mW, Supplier Part Number 1=541-3.24FFCT-ND, TempCo="100 ppm/C", Tolerance_%=1%, Value2=0.25W, Value_Code=3R24, ValueDisplayed=3.24
R96 R98: library part CMP-0023343-3, "RES, 0, 1%, 0.1 W, AEC-Q200 Grade 0, 0603", Manufacturer="Stackpole Electronics Inc", PartNumber=RMCF0603ZT0R00, Power_W=100mW, Supplier Part Number 1=RMCF0603ZT0R00CT-ND, TempCo=ppm/C, Tolerance_%=1%, Value2=0.1W, Value_Code=0
R100: library part CMP-0022601-4, "RES, 7.50 k, 1%, 0.1 W, AEC-Q200 Grade 0, 0603", Manufacturer=Vishay-Dale, Power_W=100mW, Supplier Part Number 1=541-7.50KHCT-ND, TempCo="100 ppm/C", Tolerance_%=1%, Value2=0.1W, Value_Code=7k50, ValueDisplayed=7.50k
R104: library part CMP-0025950-3, "RES, 100 k, 1%, 0.063 W, AEC-Q200 Grade 0, 0402", Manufacturer=Vishay-Dale, PartNumber=CRCW0402100KFKED, Power_W=63mW, Supplier Part Number 1=541-100KLCT-ND, TempCo="100 ppm/C", Tolerance_%=1%, Value2=0.063W, Value_Code=100k
R105 R106: library part CMP-0025830-4, "RES, 5.1 k, 5%, 0.1 W, AEC-Q200 Grade 0, 0603", Manufacturer=Vishay-Dale, Power_W=100mW, Supplier Part Number 1=541-5.1KGCT-ND, TempCo="200 ppm/C", Tolerance_%=5%, Value2=0.1W, Value_Code=5k10, ValueDisplayed=5.1k
R107 R155 R160 R163 R169: library part CMP-0021998-4, "RES, 10.0 k, 1%, 0.1 W, AEC-Q200 Grade 0, 0603", Manufacturer=Vishay-Dale, Power_W=100mW, Supplier Part Number 1=541-10.0KHCT-ND, TempCo="100 ppm/C", Tolerance_%=1%, Value2=0.1W, Value_Code=10k0, ValueDisplayed=10.0k
R110: library part CMP-0022042-4, "RES, 13.0 k, 1%, 0.1 W, AEC-Q200 Grade 0, 0603", Manufacturer=Vishay-Dale, Power_W=100mW, Supplier Part Number 1=541-13.0KHCT-ND, TempCo="100 ppm/C", Tolerance_%=1%, Value2=0.1W, Value_Code=13k0, ValueDisplayed=13.0k
R111: library part CMP-0022589-4, "RES, 75.0 k, 1%, 0.1 W, AEC-Q200 Grade 0, 0603", Manufacturer=Vishay-Dale, PartNumber=CRCW060375K0FKEA, Power_W=100mW, Supplier Part Number 1=541-75.0KHCT-ND, TempCo="100 ppm/C", Tolerance_%=1%, Value2=0.1W, Value_Code=75k0, ValueDisplayed=75.0k
R112: library part CMP-0025769-4, "RES, 2.2 k, 5%, 0.1 W, AEC-Q200 Grade 0, 0603", Manufacturer=Vishay-Dale, Power_W=100mW, Supplier Part Number 1=541-2.2KGCT-ND, TempCo="200 ppm/C", Tolerance_%=5%, Value2=0.1W, Value_Code=2k20, ValueDisplayed=2.2k
R116: library part CMP-0093991-1, "6.2 kOhms ±0.1% 0.1W, 1/10W Chip Resistor 0603 (1608 Metric) Automotive AEC-Q200 Thin Film", Digikey Part Number=P6.2KDBCT-ND, Manufacturer=Panasonic, Mouser Part Number=667-ERA-3AEB622V, Operating Temperature Range="-55°C to +155°C", Power_W=100mW, TempCo=25ppm/°C, Tolerance_%=0.1%
R118: library part CMP-0022439-4, "RES, 47.5 k, 1%, 0.1 W, AEC-Q200 Grade 0, 0603", Manufacturer=Vishay-Dale, Power_W=100mW, Supplier Part Number 1=541-47.5KHCT-ND, TempCo="100 ppm/C", Tolerance_%=1%, Value2=0.1W, Value_Code=47k5, ValueDisplayed=47.5k
R119: library part CMP-0022204-4, "RES, 20.0 k, 1%, 0.1 W, AEC-Q200 Grade 0, 0603", Manufacturer=Vishay-Dale, Power_W=100mW, Supplier Part Number 1=541-20.0KHCT-ND, TempCo="100 ppm/C", Tolerance_%=1%, Value2=0.1W, Value_Code=20k0, ValueDisplayed=20.0k
R120: library part CMP-0022597-4, "RES, 78.7 k, 1%, 0.1 W, AEC-Q200 Grade 0, 0603", Manufacturer=Vishay-Dale, Power_W=100mW, Supplier Part Number 1=541-78.7KHCT-ND, TempCo="100 ppm/C", Tolerance_%=1%, Value2=0.1W, Value_Code=78k7, ValueDisplayed=78.7k
R121: library part CMP-0025950-3, "RES, 100 k, 1%, 0.063 W, AEC-Q200 Grade 0, 0402", Manufacturer=Vishay-Dale, Power_W=63mW, Supplier Part Number 1=541-100KLCT-ND, TempCo="100 ppm/C", Value1=1%, Value2=0.063W, Value_Code=100k
R122 R126: library part CMP-0026935-3, "RES, 47 k, 5%, 0.063 W, AEC-Q200 Grade 0, 0402", Manufacturer=Vishay-Dale, Power_W=63mW, Supplier Part Number 1=541-47KJCT-ND, TempCo="200 ppm/C", Tolerance_%=5%, Value2=0.063W, Value_Code=47k0, ValueDisplayed=47k
R171 R173: library part CMP-0026414-2, "RES, 4.99 k, 1%, 0.063 W, AEC-Q200 Grade 0, 0402", Manufacturer=Vishay-Dale, Power_W=63mW, Supplier Part Number 1=541-4.99KLCT-ND, TempCo="100 ppm/C", Tolerance_%=1%, Value2=0.063W, Value_Code=4k99, ValueDisplayed=4.99k
RT3 RT4: library part CMP-0054545-2, "Thermistor NTC, 10.0k ohm, 0.5%, 0603", Manufacturer=MuRata, Power_W=100mW, Tolerance_%=0.5%
S1: library part CMP-0002328-1, "Switch, SPST, 0.05 A, 12 VDC, SMD", CurrentRating_mA=50A, Manufacturer=Diptronics
TP1 TP2 TP3 TP4 TP5 TP6 TP7 TP8 TP9 TP10 TP11 TP12 TP13 TP14 TP15 TP16 TP17 TP18 TP19 TP20 TP21 TP22 TP23 TP24 TP25 TP26 TP27 TP28 TP29 TP30 TP31 TP32 TP33 TP34 TP35 TP36 TP37 TP38 TP39 TP40 TP41 TP42 TP43 TP44 TP45 TP46 TP47 TP48 TP49 TP50 TP51 TP52 TP53 TP54 TP55 TP56 TP57 TP58 TP59 TP60 TP68 TP69 TP71 TP72 TP73 TP74 TP75 TP76 TP77 TP78 TP79 TP80 TP81 TP82 TP83 TP84: library part CMP-0003825-1, "1mm Test Point, SMT", Manufacturer=Any
U1 U2: library part CMP-0122557-1, "45-V, 13-A Digital Input 4-Channel Automotive Class-D Audio Amplifier with Current Sense and Real-time Load Diagnostics", Manufacturer="Texas Instruments", Max Supply Voltage=45V, Min Supply Voltage=4.5V, Operating Temperature Range="-55°C to +175°C", Output Current Per Channel=13A, Power At Speaker R="215W @ 4Ω"
U3: library part CMP-0079180-1, "Low Iq Always ON Smart Diode Controller, DBV0006A (SOT-23-6)", Alternate Manufacturer="Texas Instruments", Alternate PartNumber=LM74700QDBVRQ1
U4: library part CMP-0070332-1, "800mA Low-Dropout Linear Regulator, 3-pin TO-252, Pb-Free", Manufacturer="Texas Instruments", PackageTopMarking=NSUZXYTT*LM1117*IDT-3.3, PowerWise=N
U5: library part CMP-0093580-1, "3 V-36 V, 3-A Synchronous Buck Converter Optimized for Ultra Low EMI and Light Load Efficiency", Manufacturer="Texas Instruments", Max Supply Voltage=36V, Min Supply Voltage=3.6V, Nominal Supply Current=0.2-3uA, Operating Temperature Range="-40°C to +150°C", Output Voltage=1-34.2V, Switching Frequency=0.25-2.2MHz
U6: "Photolink- Fiber Optic Receiver, TH", Manufacturer=Everlight, PartNumber=PLR135/T10, Supplier Part Number 1=1080-1433-ND
U7: library part CMP-0028713-1, "Automotive Catalog 96-kHz 24-Bit Digital Audio Interface Receiver, 50 ps Jitter, 3.3V, -40 to 85 degC, 28-Pin TSSOP (PW), Green (RoHS & no Sb/Br)", Manufacturer="Texas Instruments", PartNumber=DIR9001IPWQ1, Supply Voltage(s)(V)=3.3
U8: library part CMP-0120194-1, "Wide-VIN, 2.2 MHz dual-phase boost controller with VOUT tracking", Manufacturer="Texas Instruments", Max Supply Voltage=42V, Min Supply Voltage=2.5V, Nominal Supply Current=1500uA, Operating Temperature Range="-40°C to +125°C", Output Voltage=6-60V, Switching Frequency=100-2200kHz
U9: library part CMP-0051741-1, "Automotive Catalog Single Two-Input Positive-NAND Gate, DCK0005A, LARGE T&R", F @ Nom Voltage(Max)(Mhz)=75, Generic Part Number=SN74AHC1G00-Q1, ICC @ Nom Voltage(Max)(mA)=0.01, Manufacturer="Texas Instruments", Operating Temperature Range(C)="-40 to 125", Rating=Automotive, tpd @ Nom Voltage(Max)(ns)=11.4,7.5, Voltage(Nom)(V)=3.3,5
U10: library part CMP-0120888-1, "Automotive Mixed-Signal Microcontrollers With CAN-FD Interface", Frequency_Fixed=80MHz, Manufacturer="Texas Instruments", Max Supply Voltage=3.6V, Min Supply Voltage=1.62V, Operating Temperature Range="-40°C to +125°C"
U11 U12 U13 U14: library part CMP-0091149-1, "Clock Clock Buffer IC 1:4 250MHz 8-TSSOP (0.173\", 4.40mm Width)", Digikey Part Number=296-LMK1C1102PWRCT-ND, Manufacturer="Texas Instruments", Max Supply Voltage=3.465V, Min Supply Voltage=1.71V, Mouser Part Number=595-LMK1C1102PWR, Nominal Supply Current=25-33000uA, Operating Temperature Range="-40°C to +125°C"
U15: library part CMP-0070337-2, "Space Saving 800mA Low-Dropout Linear Regulator with Internal Current Limit, NDP0003B (TO-252-3)", Manufacturer="Texas Instruments"
U16: library part CMP-0032674-1, "CAN Interface IC Automotive high speed CAN transceiver 8-SOIC -40 to 125", Digikey Part Number=296-TCAN1044VDRQ1CT-ND, Manufacturer="Texas Instruments", Max Supply Voltage=5.5V, Min Supply Voltage=4.5V, Mouser Part Number=595-TCAN1044VDRQ1, Nominal Supply Current=4.5-49mA, Operating Temperature Range="-40°C to +125°C"
Y1: library part CMP-0004590-1, "Crystal, 24.576 MHz, 10pF, SMD", Frequency Stability=+/-20ppm, Frequency_Fixed=24.576MHz, Manufacturer="Abracon Corporation", Supplier Part Number 1=535-9094-1-ND
Y2: library part CMP-0004693-3, "Crystal, 32.768 KHz, 12.5 pF, SMD", Frequency_Fixed=32.768kHz, Manufacturer=Epson
Y3: library part CMP-0098168-2, "Crystal 40MHz ±10ppm (Tol) ±20ppm (Stability) 12pF FUND 40Ohm 4-Pin Mini-CSMD T/R", Frequency Stability=20ppm, Frequency Tolerance=10ppm, Frequency_Fixed=40MHz, Load Capacitance=12pF, Manufacturer="Seiko Epson", Operating Temperature Range="-40°C to +105°C"

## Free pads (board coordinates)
  round 236.22 hole 157.48: 1(11961.37,15301.37) 1(14566.37,15301.37) 1(18336.64,15301.37)
  round 60 smd far side: 1(18540.23,12336.09)
  round 39.37 smd: 1(18541.28,12336.14)
  round 82.68 hole 82.68 unplated: 5(11715,12525) 5(18685,13235)

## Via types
v1: diameter 25, hole 12, TOP to BOTTOM, tented both sides, 1621 vias
v2: diameter 22, hole 10, TOP to BOTTOM, tented both sides, 436 vias
v3: diameter 236.22, hole 137.8, TOP to BOTTOM, 15 vias
v4: diameter 19.68, hole 7.87, TOP to BOTTOM, tented both sides, 12 vias
v5: diameter 19.68, hole 7.87, TOP to BOTTOM, 1 vias

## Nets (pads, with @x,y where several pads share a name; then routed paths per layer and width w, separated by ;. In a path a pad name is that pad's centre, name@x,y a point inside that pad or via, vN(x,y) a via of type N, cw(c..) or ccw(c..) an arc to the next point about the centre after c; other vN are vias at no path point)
3.3V-SPDIF: C126.1 C133.1 C134.2 C135.2 L18.1 Q2.2 R47.2 R53.2 R56.1 R59.1 U6.1 U7.5 U7.24 | length 4425.6
  TOP w6.5: Q2.2@16937.24,15972.4 17002.6,15972.4 17005,15970 ; v2(17050,16015) 17053.25,16015 17064.16,16025.92 17099.66,16025.92 U7.24@17101.14,16027.39 ; v2(17285,16025) 17286.2,16026.2 17332.22,16026.2 U7.5@17333.42,16027.39 ; R56.1@17461.97,16274.56 R59.1@17461.97,16309.56 v2(17461.97,16351.67)
  SIG03 w6.5: 17045,15965 17055,15965 ; U6.1@18090,12468.86 U6.1@18107,12485.86
  SIG03 w15: 17465,15965.98 17465,15806.46 18107,15164.46 18107,15137.1 U6.1@18107,12485.86
  BOTTOM w6.5: v2@17047.7,15982.7 v2(17050,15985) 17053.25,15985 17059.62,15991.37 R47.2@17082.59,15991.37 ; v2(17050,16040) 17051.22,16040 17082.28,16071.06 C134.2@17082.28,16074.99 ; R53.2@17072.28,16121.68 17072.28,16119.72 17082.28,16109.72 C134.2@17082.28,16074.99 ; C135.2@17122.28,16074.99 C134.2@17082.28,16074.99 ; v2(17285,16025) 17300.15,16009.85 C133.1@17333.7,16009.85 ; U6.1@18090,12468.86 18125,12503.86 v2(18125,12535) ; v2@18123.04,12535 C126.1@18123.04,12615
3V3: C143.2 C171.1 C199.2 C200.1 J10.3 J12.5 L17.2 R122.2 R134.2 R136.2 R152.2 R153.2 TP72.1 U10.40 U16.5 | length 6632.7
  TOP w6.5: U16.5@15404.18,16763.35 15404.18,16710.56 C171.1@15403.62,16710 15404.1,16709.52 15429.96,16709.52 v1(15430.44,16709.04) ; v2(17658.77,16130) 17658.77,16056.23 17690.31,16024.69 R152.2@18055,16024.69 R153.2@18115,16024.69
  SIG04 w6.5: 18504.88,16122.86 18507,16120.74
  SIG04 w15: J12.5@16742.07,12273.75 16808.32,12340 17205,12340 17285,12260 18310,12260 18504.88,12454.88 18504.88,16122.86
  BOTTOM w6.5: v2@17659.59,16254 v2(17659.1,16253.51) 17662.35,16253.51 17667.28,16248.57 17690.91,16248.57 17700,16239.49 17747.05,16239.49 17755,16247.44 C200.1@17755,16251.38 17755,16255.32 17777.81,16278.13 17777.81,16288.71 17811.84,16322.74 17811.84,16325.57 17821.3,16335.03 U10.40@17837.8,16335.03 ; C199.2@17699.51,16249 C199.2@17700,16249.49 ; R134.2@18441.97,16360.36 18442.15,16360.18 18479.82,16360.18 v2(18480,16360) ; R136.2@18442.32,16312.98 18443.07,16313.73 18479.25,16313.73 v2(18480,16314.48)
  BOTTOM w8: v2(17658.77,16130) 17661.45,16132.68 17661.45,16138.23 17688.52,16165.3 R122.2@17692.46,16165.3 17692.46,16222.46 C199.2@17700,16230
  other v1: 14185.49,16656.33 14225.49,16656.33 14265.49,16656.33 14185.49,16696.33 14225.49,16696.33 14265.49,16696.33
  other v2: 17485,16490 17535,16490 17485,16540 17535,16540 17485,16590 17535,16590
A0_2: R127.2 U10.26 | length 88.1
  BOTTOM w6.5: U10.26@18047.25,16121.37 18048.16,16120.47 18048.16,16078.02 18055,16071.18 R127.2@18055,16036.5
A0_3: R124.2 U10.25 | length 104.8
  BOTTOM w6.5: U10.25@18066.94,16121.37 18067.84,16120.47 18067.84,16084.53 18101.19,16051.18 18101.3,16051.18 18115,16037.48 R124.2@18115,16036.5
AGND: C181.2 C182.1 C183.2 C184.2 C185.2 C186.2 C190.2 C192.2 C194.2 C195.2 NT1.1 R64.2 R96.2 R101.2 R103.2 R107.1 R110.2 R111.1 R114.1 R118.1 R119.1 R120.1 TP84.1 U8.4 U8.33 | length 1531.4
  TOP w6.5: R101.2@13095.63,14523.5 13096.61,14522.52 13150.63,14522.52 13164.33,14508.82 13165.32,14508.82 13187.33,14486.8 v2(13253.9,14486.8) ; C190.2@13115,14419.3 13120,14424.3 C190.2@13120,14425 ; C190.2@13130,14425 13135,14430 v2(13235,14430) TP84.1@13280,14430
  TOP w8: v2(12905,14475) 12905,14478.79 12912.13,14485.92 12912.13,14524 12918.13,14530 R111.1@12925.63,14530
  BOTTOM w6.5: v2(12848,14644.37) C194.2@12876.61,14644.37 C194.2@12878.11,14645.87 ; v2(12905,14475) 12905,14511.73 C186.2@12905.8,14512.53 C185.2@12967.63,14512.53 ; U8.4@13068.67,14785.79 13153.32,14785.79 U8.33@13163.16,14795.63 ; R110.2@13202.26,14523.5 R107.1@13253.54,14523.5 ; R118.1@13205,14430 R118.1@13206.5,14430 v2(13235,14430) ; v2(13253.9,14486.8) R107.1@13253.9,14523.15 ; R107.1@13254.26,14523.5 13254.26,14524.49 13267.96,14538.19 13268.95,14538.19 13276.62,14545.86 13284.9,14545.86 13292.57,14538.19 13293.56,14538.19 13307.26,14524.49 R103.2@13307.26,14523.5 13305,14521.24 v2(13305,14485) ; R96.2@13424.79,14697.8 13428.37,14701.37 v2(13459.37,14701.37) 13461.13,14701.37 13517.5,14645 R120.1@13525,14645 ; R64.2@13446.07,14890.39 R64.2@13445.09,14890.39 13460.77,14905.09 v2(13550,14910) ; C183.2@13448.21,15062.78 13463.89,15048.08 13530.77,15007.51 C182.1@13552.36,14975.1 13550,14942.68 v2(13550,14910) ; C181.2@13566.5,14860 13550.81,14874.7 v2(13550,14910)
  BOTTOM w8: v2(12805,14670) R119.1@12805,14700 12857.52,14700 C195.2@12863.17,14705.65 ; v2(12825,14795) 12866.42,14795 C192.2@12867.42,14796 ; v2(12840,14980) 12873.5,14980 C184.2@12878.5,14985
  other v4: 13138.36,14732.64 13187.96,14732.64 13100.17,14770.83 13138.36,14770.83 13187.96,14770.83 13226.15,14770.83 13100.17,14820.43 13138.36,14820.43 13187.96,14820.43 13226.15,14820.43 13138.36,14858.62 13187.96,14858.62
ATRK/DTRK: C185.1 C186.1 C187.2 R104.1 R105.1 R111.2 U8.32 | length 831.6
  TOP w6.5: R111.2@12925.63,14590 12972.13,14590 R105.1@12980.63,14581.5 12985.63,14586.5 v2(12985.63,14620.78)
  SIG04 w6.5: v2(12985.63,14620.78) 13012.32,14594.09 13354.09,14594.09 v2(13355,14595)
  BOTTOM w6.5: C187.2@12840,14586.57 12894.75,14586.57 C186.1@12905.8,14575.52 C185.1@12967.63,14575.52 12967.63,14602.78 12986.23,14621.38 13006.38,14621.38 13030,14645 13042.35,14645 13089.94,14692.58 13092.59,14692.58 13094.26,14694.25 U8.32@13094.26,14701.14 ; R104.1@13355,14575 v2(13355,14595)
BAT_IN: C109.1 C110.1 C111.1 C112.1 C113.1 J1.1 J1.3 J1.5 J1.7 J1.9 J1.11 L12.1 TP59.1
  other v1: 12810.22,12845.99 12855.22,12845.99 12900.22,12845.99 12810.22,12895.99 12855.22,12895.99 12900.22,12895.99 12810.22,12945.99 12855.22,12945.99 12900.22,12945.99 12810.22,12995.99 12855.22,12995.99 12900.22,12995.99 12810.22,13045.99 12855.22,13045.99 12900.22,13045.99 12810.22,13095.99 12855.22,13095.99 12900.22,13095.99 12810.22,13145.99 12855.22,13145.99 12900.22,13145.99 12810.22,13195.99 12855.22,13195.99 12810.22,13245.99 12855.22,13245.99 12810.22,13295.99 12855.22,13295.99 12810.22,13345.99 12855.22,13345.99 12900.22,13345.99 12810.22,13395.99 12855.22,13395.99 12900.22,13395.99 12810.22,13445.99 12855.22,13445.99 12900.22,13445.99 12950.22,13445.99 13000.22,13445.99 12810.22,13495.99 12855.22,13495.99 12900.22,13495.99 12950.22,13495.99 13000.22,13495.99 12810.22,13545.99 12855.22,13545.99 12900.22,13545.99 12950.22,13545.99 13000.22,13545.99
